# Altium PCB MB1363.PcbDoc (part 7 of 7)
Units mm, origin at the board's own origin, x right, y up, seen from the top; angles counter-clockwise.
Board outline 70 x 133.34 mm, 6 copper layers (Top Layer, Signal Layer 1, Signal Layer 2, Signal Layer 3, Signal Layer 4, Bottom Layer), stack 1.57 mm thick; 356 components, 294 nets, 1448 pads, 1107 vias.
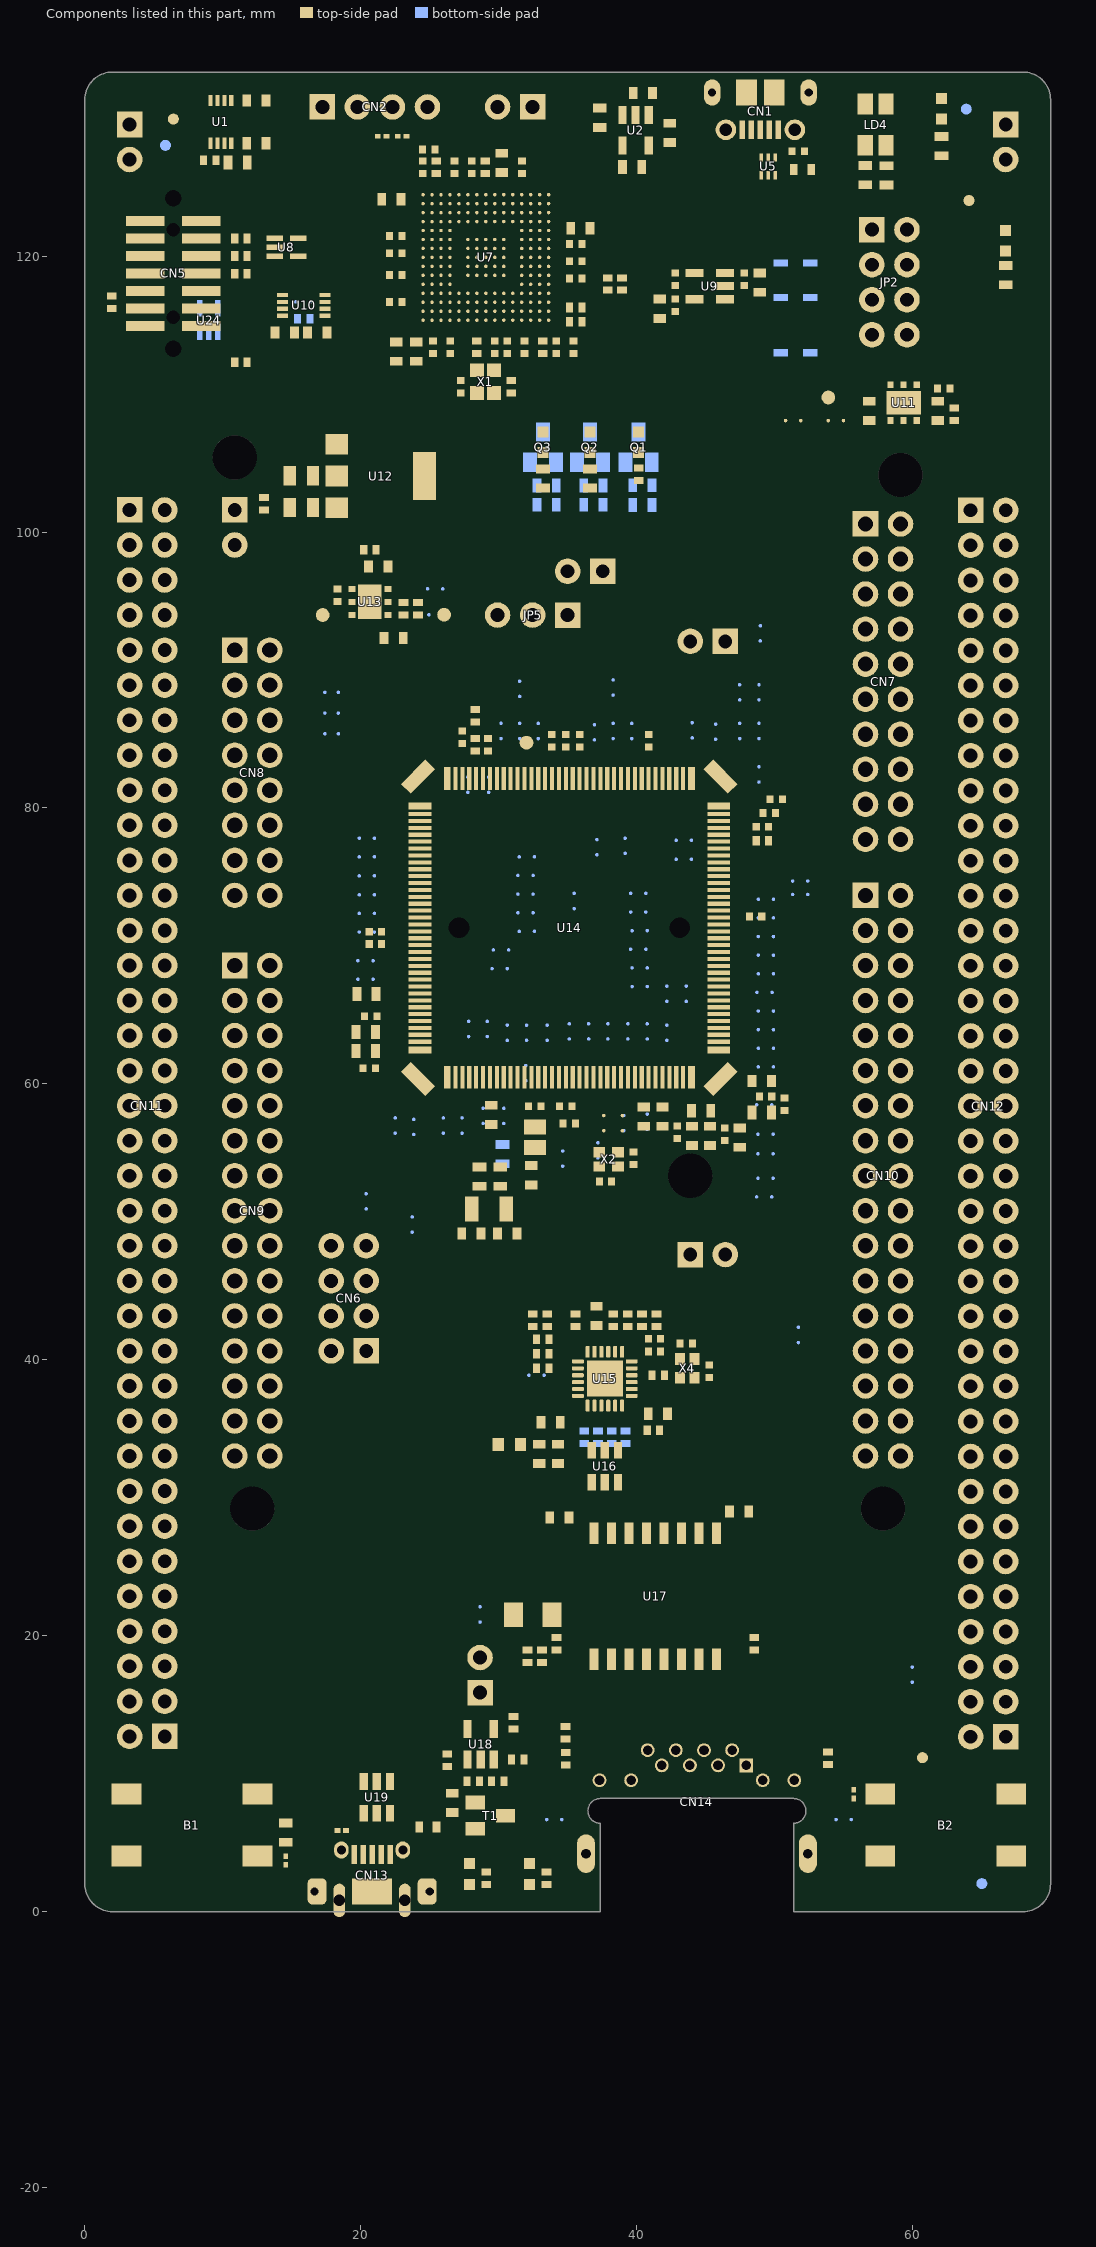
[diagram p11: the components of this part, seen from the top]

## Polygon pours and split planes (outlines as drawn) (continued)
GND on Top Layer "GND_L01_P090" (solid, remove dead copper, pour order 90): 1.577,133.34 0.116,131.879 0.116,107.629 20.166,107.629 20.666,108.129 25.866,108.129 26.4,107.595 26.4,100.163 25.991,99.754 16.291,99.754 15.416,100.629 13.866,100.629 13.866,107.629 0.116,107.629 0.116,1.629 1.616,0.129 35.366,0.129 35.366,12.379 28.991,12.379 28.616,12.004 28.616,8.979 27.016,7.379 26.266,7.379 25.366,6.479 25.366,4.379 23.866,2.879 21.866,2.879 21.366,3.379 21.366,5.379 25.116,9.129 25.116,14.629 25.366,14.879 35.866,14.879 35.866,8.379 53.366,8.379 53.369,0 68.237,0 69.866,1.629 69.866,106.879 60.116,106.879 59.616,107.379 59.616,108.629 59.866,108.879 63.116,108.879 63.116,111.879 62.616,112.379 59.016,112.379 58.15,113.245 58.15,124.05 58.979,124.879 63.616,124.879 64.366,124.129 64.366,119.379 64.866,118.879 67.396,118.879 67.396,118.849 67.866,118.379 67.866,107.629 67.616,107.379 67.616,107.129 69.866,107.129 69.866,131.879 68.405,133.34
5V on Signal Layer 2 "5V_L03_P060" (solid, remove dead copper, pour order 60): 58.575,113.8 59.496,112.879 62.391,112.879 63.616,114.104 63.616,124.429 61.641,126.404 50.866,126.404 48.191,123.729 41.841,123.729 36.066,117.954 26.266,117.954 23.766,120.454 4.541,120.454 1.091,117.004 1.091,113.079 1.691,112.479 3.941,112.479 5.466,114.004 38.241,114.004 44.791,120.554 57.771,120.554 58.63,119.695
5V_VIN on Signal Layer 2 "5V_VIN_L03_P034" (solid, remove dead copper, pour order 34): 19.366,104.779 20.316,105.729 20.316,107.504 20.666,107.854 25.641,107.854 26.016,107.479 26.016,100.629 25.666,100.279 20.491,100.279 20.291,100.479 20.291,102.429 19.591,103.129 19.366,103.354
VDD_MCU on Signal Layer 2 "VDD_MCU_L03_P088" (solid, remove dead copper, pour order 88): 18.166,87.354 17.916,87.104 17.916,86.479 18.266,86.129 24.191,86.129 27.941,82.379 41.591,82.379 42.166,82.954 42.166,85.304 41.641,85.829 31.891,85.829 30.366,87.354
5V on Signal Layer 2 "5V_L03_P062" (solid, remove dead copper, pour order 62): 15.866,14.304 13.316,11.754 1.441,11.754 1.091,11.404 1.091,9.979 1.716,9.354 14.791,9.354 17.816,12.379 27.091,12.379 27.366,12.654 27.366,14.079 27.141,14.304
VIN on Signal Layer 2 "VIN_L03_P082" (solid, remove dead copper, pour order 82): 12.441,104.079 12.016,104.079 11.191,103.254 11.191,101.679 12.566,100.304 19.716,100.304 19.991,100.579 19.991,102.279 19.366,102.904 18.196,104.074 17.341,104.074
GND on Signal Layer 2 "GND_L03_P092" (solid, remove dead copper, pour order 92): 2,133.34 1.986,133.354 1.55,133.354 -0.009,131.795 -0.009,117.504 0.166,117.329 0.916,117.329 4.391,120.804 23.941,120.804 26.391,118.354 35.841,118.354 41.566,124.079 48.041,124.079 50.816,126.854 62.041,126.854 64.016,124.879 64.016,114.004 62.841,112.829 62.841,112.079 69.816,112.079 69.816,132.004 68.491,133.329
GND on Signal Layer 2 "GND_L03_P094" (solid, remove dead copper, pour order 94): 0.091,113.329 0.391,113.329 1.491,112.229 4.166,112.229 5.641,113.704 38.666,113.704 45.116,120.154 57.671,120.154 58.225,119.6 58.225,113.675 59.346,112.554 62.566,112.554 62.841,112.829 69.592,112.829 69.866,112.555 69.866,81.879 43.116,81.879 42.366,82.629 42.366,83.559 42.366,85.429 41.766,86.029 31.966,86.029 26.366,91.629 26.366,107.654 25.716,108.304 20.491,108.304 19.891,107.704 19.891,105.829 18.466,104.404 11.741,104.404 10.716,103.379 10.716,100.529 10.566,100.379 0.341,100.379 0.091,100.629
GND on Signal Layer 2 "GND_L03_P096" (solid, remove dead copper, pour order 96): 26.666,100.854 25.916,100.104 12.241,100.104 10.4,101.945 10.4,103.669 8.751,103.669 7.491,104.929 0.216,104.929 0.116,104.829 0.116,11.404 0.253,11.266 0.579,11.266 1.316,12.004 13.166,12.004 15.691,14.529 27.316,14.529 27.616,14.229 27.616,12.179 69.916,12.179 69.941,12.204 69.941,81.577 69.59,81.929 43.066,81.929 42.366,82.629 41.741,82.004 27.741,82.004 23.891,85.854 18.141,85.854 17.616,86.379 17.616,87.204 18.091,87.679 30.287,87.679 30.301,87.693 26.666,91.329
GND on Signal Layer 2 "GND_L03_P098" (solid, remove dead copper, pour order 98): 0.566,10.029 1.616,8.979 15.041,8.979 18.116,12.054 27.141,12.054 27.666,12.579 34.091,12.579 34.416,12.904 34.416,13.054 35.291,13.929 69.891,13.929 69.941,13.879 69.941,1.204 68.816,0.079 1.216,0.079 0.216,1.079 0.216,10.004 0.191,10.029
GND on Signal Layer 1 "GND_L02_P020" (solid, remove dead copper, pour order 20): 35.266,9.866 36.068,10.668 52.748,10.668 53.666,9.75 53.666,8.429 53.491,8.254 53.491,0 69.037,0 69.416,0.379 70,0.963 70,132.345 69.005,133.34 68,133.34 -0.034,133.379 -0.034,0.929 0.895,0 35.266,0
GND on Signal Layer 4 "GND_L05_P050" (solid, remove dead copper, pour order 50): 35.369,10.569 36.425,11.625 52.4,11.625 53.425,10.6 53.364,10.263 53.501,10.126 53.5,10 53.525,9.975 53.541,9.975 53.541,0.054 53.591,0.079 68.541,0.079 69.866,1.404 69.866,131.829 68.466,133.229 1.791,133.254 1.516,133.254 0.041,131.779 0.041,1.629 1.591,0.079 35.369,0.079

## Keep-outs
Keep-Out Layer:
  lines w0.127: -0.004,1.999 ccw(c1.996,1.999) 1.996,-0.001

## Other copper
Top Layer:
  pour cut-out: 33.041,51.529 31.941,51.529 30.991,52.479 30.991,53.904 30.191,54.704 30.191,55.529 30.941,56.279 30.941,57.979 31.541,58.579 31.541,61.329 31.691,61.479 35.066,61.479 35.191,61.354 35.191,59.329 35.716,58.804 36.216,58.804 36.991,58.029 36.991,56.879 36.316,56.204 36.316,55.604 33.916,53.204 33.916,52.278 33.166,51.528
  pour cut-out: 24.316,126.629 23.271,126.629 21.721,125.079 21.721,122.206 21.536,122.021 21.536,113.804 22.001,113.339 26.226,113.339 26.891,114.004 26.891,115.779 27.446,116.334 28.79,116.334 29.716,115.408 29.716,113.904 30.416,113.204 35.791,113.204 36.291,113.704 36.291,121.204 36.116,121.379 31.791,121.379 31.791,122.379 32.49,123.078 32.49,126.627
  pour cut-out: 48.616,126.679 48.616,126.254 49.966,126.254 49.966,126.734 48.621,126.734 48.616,126.729
  pour cut-out: 35.366,17.35 53.366,17.35 53.366,-0.121 35.366,-0.121
  pour cut-out: 29.6,22.95 36.366,22.95 36.366,0 29.6,0
  text "1" at 67.218,104.184 h2 r90
Signal Layer 1:
  pour cut-out: 33.041,51.529 31.941,51.529 30.991,52.479 30.991,53.904 30.191,54.704 30.191,55.529 30.941,56.279 30.941,57.979 31.541,58.579 31.541,61.329 31.691,61.479 35.066,61.479 35.191,61.354 35.191,59.329 35.716,58.804 36.216,58.804 36.991,58.029 36.991,56.879 36.316,56.204 36.316,55.604 33.916,53.204 33.916,52.278 33.166,51.528
  pour cut-out: 35.366,17.35 53.366,17.35 53.366,-0.121 35.366,-0.121
  pour cut-out: 29.6,22.95 36.366,22.95 36.366,0 29.6,0
  text "2" at 67.218,105.434 h2 r90
Signal Layer 2:
  pour cut-out: 33.041,51.529 31.941,51.529 30.991,52.479 30.991,53.904 30.191,54.704 30.191,55.529 30.941,56.279 30.941,57.979 31.541,58.579 31.541,61.329 31.691,61.479 35.066,61.479 35.191,61.354 35.191,59.329 35.716,58.804 36.216,58.804 36.991,58.029 36.991,56.879 36.316,56.204 36.316,55.604 33.916,53.204 33.916,52.278 33.166,51.528
  pour cut-out: 35.366,17.35 53.366,17.35 53.366,-0.121 35.366,-0.121
  pour cut-out: 30.125,23.025 36.366,23.025 36.366,0 30.125,0
  text "3" at 67.218,106.934 h2 r90
Signal Layer 3:
  pour cut-out: 35.325,17.421 53.325,17.421 53.325,-0.05 35.325,-0.05
  text "4" at 67.218,109.184 h2 r90
Signal Layer 4:
  pour cut-out: 37.266,61.429 37.216,61.379 37.141,61.304 37.141,58.929 36.966,58.754 36.966,55.804 36.191,55.029 36.191,52.079 36.641,51.629 38.866,51.629 40.741,53.504 40.741,55.404 40.091,56.054 39.591,56.554 39.591,58.554 39.216,58.929 39.216,61.329 39.116,61.429
  pour cut-out: 30.741,61.429 30.666,61.354 30.666,58.729 30.391,58.454 30.391,57.929 30.066,57.604 29.066,57.604 28.841,57.379 28.841,56.604 27.666,55.429 27.666,52.729 26.866,51.929 26.866,48.504 27.541,47.829 30.966,47.829 31.791,48.654 31.791,51.154 30.841,52.104 30.841,54.204 30.641,54.404 30.291,54.404 30.216,54.479 30.216,55.554 31.016,56.354 31.016,58.129 31.591,58.704 31.591,61.354 31.516,61.429
  pour cut-out: 35.366,17.35 53.366,17.35 53.366,-0.121 35.366,-0.121
  pour cut-out: 32.3,8.2 36.366,8.2 36.366,0 32.3,0
  pour cut-out: 52.225,8.2 56.291,8.2 56.291,0 52.225,0
  text "5" at 67.218,110.684 h2 r90
Bottom Layer:
  pour cut-out: 32.541,19.7 35.475,19.7 35.475,0 32.541,0
  pour cut-out: 32.575,17.366 32.575,20.3 56.325,20.3 56.325,17.366
  pour cut-out: 56.459,0 53.525,0 53.525,20.225 56.459,20.225
  text "6" at 67.218,112.184 h2 r90
Multi-Layer:
  pour cut-out: 65.621,103.891 67.621,103.891 67.621,112.391 65.621,112.391
  pour cut-out: 36.441,28.325 36.441,17.359 46.266,17.359 46.266,28.325

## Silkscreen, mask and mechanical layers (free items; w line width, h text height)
Top Overlay:
  drawing of 1859 lines, arcs and shapes, not listed
  text "OVCR" at 60.186,132.098 h1.5
  text "COM" at 55.903,132.049 h1.5
  text "SWD" at 27.254,129.311 h1.5 r90
  text "STLK_RST" at 29.705,128.396 h0.91
  text "3V3" at 15.966,128.329 h1.5
  text "USB" at 45.027,127.236 h1.5
  text "STLK" at 15.394,127.064 h1.5
  text "GND" at 1.547,126.954 h1.5 r90
  text "GND" at 69.474,126.947 h1.5 r90
  text "PWR" at 44.861,126.086 h1.5
  text "ST-LINK V3" at 34.721,123.685 h1.5
  text "STLINK" at 50.42,121.407 h1.5
  text "VIN" at 52.85,118.795 h1.5
  text "5V" at 62.324,118.566 h1.5
  text "PWR" at 61.689,117.042 h1.5
  text "EXT" at 52.552,116.332 h1.5
  text "RX" at 0.706,114.299 h1.5
  text "TX" at 10.391,114.299 h1.5
  text "CHGR" at 51.18,113.769 h1.5
  text "MIPI10" at 4.326,111.224 h1.5
  text "3V3" at 52.749,110.764 h1.5
  text "5V_VIN" at 25.824,103.769 h1.5
  text "SCL" at 60.916,101.154 h1.2 r45
  text "User LEDs" at 34.039,101.13 h1.5
  text "D15" at 60.991,100.029 h1.2 r45
  text "VIN" at 17.315,99.842 h1.5
  text "3V3" at 36.435,98.66 h1.5
  text "SDA" at 60.916,98.379 h1.2 r45
  text "D14" at 60.991,97.229 h1.2 r45
  text "IDD" at 39.875,96.65 h1.5
  text "MCU_RST" at 7.776,96.466 h1.5
  text "+" at 62.291,95.379 h1.2 r45
  text "VREF" at 60.966,95.204 h1.2 r45
  text "I2S_A" at 54.017,94.409 h1.5 r90
  text "VDD" at 37.108,94.261 h1.5
  text "MCU" at 37.124,93.168 h1.5
  text "GND" at 60.891,92.779 h1.2 r45
  text "NC" at 7.741,92.154 h1.2 r315
  text "1V8" at 24.965,92.119 h1.5
  text "1V8" at 28.66,91.244 h1.5
  text "3V3" at 34.158,91.226 h1.5
  text "VDD" at 24.698,90.979 h1.5
  text "SCK" at 60.916,90.904 h1.2 r45
  text "VDD" at 28.393,90.104 h1.5
  text "VDD" at 33.891,90.086 h1.5
  text "D13" at 61.016,89.779 h1.2 r45
  text "IO" at 8.216,89.754 h1.2 r315
  text "RMII TXD1" at 41.862,89.533 h1.5
  text "REF" at 7.491,89.004 h1.2 r315
  text "MISO" at 60.966,88.079 h1.2 r45
  text "NRST" at 7.116,86.904 h1.2 r315
  text "D12" at 61.016,86.879 h1.2 r45
  text "I2S_B" at 54.719,85.921 h1.5 r90
  text "MOSI" at 60.991,85.329 h1.2 r45
  text "D11" at 60.966,84.079 h1.2 r45
  text "3V3" at 7.716,83.904 h1.2 r315
  text "SDMMC" at 16.676,82.753 h1.5 r90
  text "CS" at 60.891,82.629 h1.2 r45
  text "D10" at 60.966,81.479 h1.2 r45
  text "5V" at 7.841,81.354 h1.2 r315
  text "PWM" at 60.991,80.104 h1.2 r45
  text "GND" at 7.441,79.054 h1.2 r315
  text "D9" at 61.016,78.904 h1.2 r45
  text "SPI_B" at 54.151,78.837 h1.5 r90
  text "I/O" at 61.016,77.429 h1.2 r45
  text "GND" at 7.416,76.479 h1.2 r315
  text "D8" at 61.016,76.229 h1.2 r45
  text "IO" at 16.64,74.292 h1.5 r90
  text "I/O" at 61.041,74.204 h1.2 r45
  text "VIN" at 7.466,73.879 h1.2 r315
  text "AVDD" at 51.445,73.179 h1.5
  text "D7" at 61.041,72.954 h1.2 r45
  text "PWM" at 61.016,71.554 h1.2 r45
  text "AGND" at 51.342,70.602 h1.5
  text "D6" at 61.041,70.404 h1.2 r45
  text "A0" at 7.758,69.168 h1.2 r315
  text "PWM" at 61.041,69.029 h1.2 r45
  text "GND" at 52.309,68.223 h1.5
  text "D5" at 61.041,67.854 h1.2 r45
  text "A1" at 7.841,66.679 h1.2 r315
  text "I/O" at 61.016,66.429 h1.2 r45
  text "D4" at 61.041,65.204 h1.2 r45
  text "A2" at 7.866,64.129 h1.2 r315
  text "PWM" at 61.016,63.729 h1.2 r45
  text "D3" at 61.016,62.504 h1.2 r45
  text "A3" at 7.766,61.479 h1.2 r315
  text "USART" at 16.249,61.35 h1.5 r90
  text "I/O" at 61.016,61.129 h1.2 r45
  text "D2" at 61.041,59.954 h1.2 r45
  text "ADC_IN" at 54.018,59.134 h1.5 r90
  text "A4" at 7.816,59.004 h1.2 r315
  text "TX" at 60.992,58.483 h1.2 r45
  text "D1" at 60.991,57.254 h1.2 r45
  text "A5" at 7.766,56.429 h1.2 r315
  text "RX" at 61.016,55.729 h1.2 r45
  text "GND" at 14.885,55.395 h1.5
  text "D0" at 61.041,54.554 h1.2 r45
  text "COMP" at 8.392,50.222 h1.5 r90
  text "QSPI" at 53.866,49.124 h1.5 r90
  text "SAI_A" at 16.036,47.769 h1.5 r90
  text "PG" at 22.068,47.578 h1.5
  text "GND" at 24.847,47.553 h1.5
  text "VOUT" at 24.536,45.919 h1.5
  text "SW" at 21.903,45.271 h1.5
  text "RMII MDIO" at 42.543,45.101 h1.5
  text "I2C" at 8.534,44.676 h1.5 r90
  text "CORE" at 24.536,44.649 h1.5
  text "EN" at 21.996,42.744 h1.5
  text "VDD" at 24.872,42.73 h1.5
  text "TIMER" at 62.301,41.166 h1.5 r90
  text "GND" at 7.366,41.129 h1.2 r315
  text "V1" at 21.996,40.204 h1.5
  text "GND" at 52.309,40.207 h1.5
  text "3V3" at 25.093,40.186 h1.5
  text "SAI_B" at 16,37.601 h1.5 r90
  text "CAN" at 8.356,35.361 h1.5 r90
  text "TIMER" at 54.094,33.405 h1.5 r90
  text "IO" at 14.929,32.577 h1.5
  text "IO" at 8.202,32.51 h1.5
  text "USB PWR EN" at 28.325,20.05 h1.5 r90
  text "MB1363C" at 51.85,18.252 h2
  text "Nucleo" at 8.344,16.62 h3.3
  text "GND" at 64.243,10.076 h1.5
  text "GND" at 3.214,9.991 h1.5
  text "RESET" at 60.307,1.922 h1.5
  text "USER" at 6,1.9 h1.5
  text "User" at 13.205,1.729 h1.5
  text "USB" at 13.229,0.491 h1.5
  text "OVCR" at 26.258,0.329 h1.5
  text "VBUS" at 31.537,0.337 h1.5
Bottom Overlay:
  lines w0.12: 32.077,58.881 32.077,59.33
  lines w0.127: 30.875,16.45 30.875,25.45 55.875,25.45 55.875,16.45 30.875,16.45
  text "GND" at 68.326,127 h1.5 r270
  text "GND" at 0.741,126.829 h1.5 r270
  text "CN12" at 65.375,103.25 h1.5
  text "CN11" at 6.265,103.098 h1.5
  text "CN7" at 57.199,102.184 h1.5
  text "PC8" at 69.591,102.183 h1.2 r45
  text "PC11" at 9.533,101.167 h1.2
  text "PC10" at 1.766,100.979 h1.2 r315
  text "PC9" at 62.961,100.938 h1.2
  text "PC6" at 69.743,99.872 h1.2 r45
  text "PC12" at 1.791,98.579 h1.2 r315
  text "PD2" at 9.088,98.525 h1.2
  text "PB8" at 62.961,98.398 h1.2
  text "PC5" at 69.769,97.23 h1.2 r45
  text "3V3" at 1.866,96.504 h1.2 r315
  text "E5V" at 9.088,95.935 h1.2
  text "PB9" at 62.961,95.858 h1.2
  text "VDD" at 1.671,95.381 h1.2 r315
  text "U5V" at 69.667,94.563 h1.2 r45
  text "GND" at 9.088,93.445 h1.2
  text "BT0" at 1.595,93.318 h1.2 r315
  text "CN8" at 13.547,92.934 h1.5
  text "VREF+" at 62.69,92.664 h1.2 r315
  text "PD8" at 69.667,92.099 h1.2 r45
  text "NC" at 8.391,91.054 h1.2
  text "PF6" at 1.671,90.778 h1.2 r315
  text "GND" at 62.961,90.778 h1.2
  text "PA12" at 69.769,89.153 h1.2 r45
  text "+3V3" at 9.748,88.365 h1.2
  text "PA5" at 62.961,88.238 h1.2
  text "PF7" at 1.671,88.137 h1.2 r315
  text "PA11" at 69.489,86.41 h1.2 r45
  text "PA6" at 62.961,85.698 h1.2
  text "NRST" at 9.698,85.648 h1.2
  text "PA13" at 2.078,84.911 h1.2 r315
  text "PB12" at 69.591,83.895 h1.2 r45
  text "3V3" at 9.088,83.285 h1.2
  text "PA7" at 62.961,83.158 h1.2
  text "PA14" at 2.078,82.346 h1.2 r315
  text "PB11" at 69.642,81.38 h1.2 r45
  text "+5V" at 9.088,80.695 h1.2
  text "PB6" at 62.961,80.618 h1.2
  text "PA15" at 2.078,79.856 h1.2 r315
  text "GND" at 69.769,79.323 h1.2 r45
  text "GND" at 9.088,78.231 h1.2
  text "PC7" at 62.961,78.078 h1.2
  text "GND" at 1.671,78.053 h1.2 r315
  text "PB2" at 69.642,76.783 h1.2 r45
  text "GND" at 9.088,75.691 h1.2
  text "PA9" at 62.961,75.538 h1.2
  text "PB7" at 1.671,75.513 h1.2 r315
  text "CN10" at 59.578,75.041 h1.5
  text "PB1" at 69.489,74.065 h1.2 r45
  text "VIN" at 8.936,73.024 h1.2
  text "PA8" at 62.961,72.998 h1.2
  text "PC13" at 2.078,72.313 h1.2 r315
  text "PB15" at 69.591,71.373 h1.2 r45
  text "NC" at 8.466,70.704 h1.2
  text "PB10" at 62.961,70.458 h1.2
  text "CN9" at 13.647,69.951 h1.5
  text "PC14" at 2.078,69.696 h1.2 r315
  text "PB14" at 69.642,68.757 h1.2 r45
  text "PA0" at 9.088,68.096 h1.2
  text "PB4" at 62.961,67.918 h1.2
  text "PC15" at 1.9,67.36 h1.2 r315
  text "PB13" at 69.794,66.344 h1.2 r45
  text "PA1" at 8.783,65.505 h1.2
  text "PB5" at 62.961,65.378 h1.2
  text "OSCI" at 2.078,64.642 h1.2 r315
  text "AGND" at 69.86,64.007 h1.2 r45
  text "PA4" at 9.088,63.067 h1.2
  text "PB3" at 62.961,62.838 h1.2
  text "OSCO" at 2.078,62.102 h1.2 r315
  text "PC4" at 69.616,61.695 h1.2 r45
  text "PB0" at 9.088,60.425 h1.2
  text "PA10" at 62.961,60.298 h1.2
  text "VBAT" at 2.078,59.536 h1.2 r315
  text "NC" at 69.391,57.979 h1.2
  text "PC1" at 8.783,57.809 h1.2
  text "PA2" at 62.961,57.758 h1.2
  text "PC2" at 1.671,57.454 h1.2 r315
  text "NC" at 69.391,55.504 h1.2
  text "PC0" at 9.088,55.32 h1.2
  text "PA3" at 62.961,55.218 h1.2
  text "PC3" at 1.671,54.863 h1.2 r315
  text "PE8" at 69.616,53.847 h1.2 r45
  text "PD3" at 9.088,52.755 h1.2
  text "GND" at 62.961,52.678 h1.2
  text "PD4" at 1.595,52.628 h1.2 r315
  text "PF10" at 69.87,51.332 h1.2 r45
  text "NC" at 8.491,50.379 h1.2
  text "PD13" at 62.961,50.138 h1.2
  text "PD5" at 1.57,50.113 h1.2 r315
  text "PE7" at 69.667,48.716 h1.2 r45
  text "NC" at 8.516,47.904 h1.2
  text "PD6" at 1.57,47.598 h1.2 r315
  text "PD12" at 62.961,47.598 h1.2
  text "PD14" at 69.819,46.176 h1.2 r45
  text "PE2" at 9.088,45.16 h1.2
  text "PD7" at 1.519,45.135 h1.2 r315
  text "PD11" at 62.961,45.058 h1.2
  text "PD15" at 69.667,43.509 h1.2 r45
  text "PE4" at 9.088,42.747 h1.2
  text "PE3" at 1.544,42.544 h1.2 r315
  text "PE10" at 62.961,42.518 h1.2
  text "PF14" at 69.718,40.994 h1.2 r45
  text "GND" at 1.595,40.105 h1.2 r315
  text "PE12" at 62.961,39.978 h1.2
  text "PE5" at 9.088,39.928 h1.2
  text "PE9" at 69.667,38.556 h1.2 r45
  text "NC" at 1.966,37.729 h1.2
  text "NC" at 8.566,37.679 h1.2
  text "PE14" at 62.961,37.438 h1.2
  text "GND" at 69.667,36.041 h1.2 r45
  text "NC" at 2.016,35.179 h1.2
  text "PF8" at 9.088,35 h1.2
  text "PE15" at 62.961,34.898 h1.2
  text "PE11" at 69.794,33.578 h1.2 r45
  text "PF9" at 9.088,32.46 h1.2
  text "PD1" at 1.671,32.384 h1.2 r315
  text "PE13" at 62.961,32.358 h1.2
  text "NC" at 8.591,30.129 h1.2
  text "NC" at 62.941,30.054 h1.2
  text "NC" at 69.441,30.054 h1.2
  text "PD0" at 1.671,29.793 h1.2 r315
  text "PF15" at 69.819,28.32 h1.2 r45
  text "NC" at 1.916,27.554 h1.2
  text "GND" at 9.191,27.504 h1.2
  text "NC" at 62.991,27.479 h1.2
  text "PF11" at 69.642,25.704 h1.2 r45
  text "PE6" at 9.088,24.815 h1.2
  text "PG14" at 62.961,24.738 h1.2
  text "PE1" at 1.595,24.688 h1.2 r315
  text "PE0" at 69.667,23.468 h1.2 r45
  text "NC" at 8.566,22.454 h1.2
  text "GND" at 62.961,22.198 h1.2
  text "PG9" at 1.62,22.097 h1.2 r315
  text "PG8" at 69.616,20.827 h1.2 r45
  text "PG10" at 9.829,19.887 h1.2
  text "PD10" at 62.961,19.658 h1.2
  text "PG12" at 2.078,18.871 h1.2 r315
  text "PG7" at 62.925,17.475 h1.2
  text "NC" at 69.416,17.379 h1.2
  text "NC" at 2.016,17.354 h1.2
  text "PG13" at 9.829,17.322 h1.2
  text "PG6" at 69.743,15.975 h1.2 r45
  text "PG11" at 9.829,14.909 h1.2
  text "NC" at 62.841,14.754 h1.2
  text "PD9" at 1.671,14.477 h1.2 r315
  text "MB1363C" at 55.75,14.1 h2.5
  text "GND" at 67.075,10.1 h1.5
  text "GND" at 6.1,10 h1.5
Top Solder:
  region: 67.625,103.9 67.625,112.4 65.625,112.4 65.625,103.9
Bottom Solder:
  region: 67.625,103.9 67.625,112.4 65.625,112.4 65.625,103.9
M1-Board Shape:
  lines w0.1: 51.369,6.4 ccw(c51.369,6.4) 51.369,6.4 ; 51.369,6.4 ccw(c51.369,7.3) 52.269,7.3 ; 51.369,6.4 51.369,0 68,0 ; 52.269,7.3 ccw(c51.369,7.3) 51.369,8.2 37.369,8.2 ccw(c37.369,7.3) 36.469,7.3 ccw(c37.369,7.3) 37.369,6.4 37.369,0 2,0 cw(c2,2) 0,2 0,131.34 cw(c2,131.34) 2,133.34 68,133.34 cw(c68,131.34) 70,131.34 70,2 cw(c68,2) 68,0 ; 52.269,7.3 52.269,7.3 ; 68,0 68,0
Drill Drawing:
  drawing of 561 lines, arcs and shapes, not listed
  text "PCB SPECIFICATIONS :" at 2.036,176.169 h3
  text "PCB : TYPE 3" at 150.448,175.937 h3
  text "A.   MATERIAL :" at 2.036,172.169 h3
  text "FR-4" at 40.536,172.169 h3
  text "TG-170" at 57.036,172.169 h3
  text "X  TG-150" at 75.286,172.169 h3
  text "TG-140" at 91.286,172.169 h3
  text "ASPECT-RATIO, AXE Z :" at 150.448,170.437 h3
  text "B.   MATERIAL FAMILY :" at 2.036,169.169 h3
  text "N/A" at 40.536,169.169 h3
  text "C.   SOLDERMASK COLOR :" at 2.036,166.169 h3
  text "GREEN" at 40.536,166.169 h3
  text "X  WHITE" at 57.036,166.169 h3
  text "RED" at 75.286,166.169 h3
  text "BLACK" at 91.286,166.169 h3
  text "6:1 to 8:1 / LEVEL \"B\"" at 150.466,163.689 h3
  text "D.   SILKSCREEN COLOR :" at 2.036,163.169 h3
  text "WHITE" at 40.536,163.169 h3
  text "YELLOW" at 57.036,163.169 h3
  text "BLACK" at 75.286,163.169 h3
  text "X  Blue ink PANTONE 2955" at 91.286,163.169 h3
  text "E.   SURFACE FINISH :" at 2.036,160.169 h3
  text "X  ENIG" at 40.536,160.169 h3
  text "IMMERSION SILVER" at 57.036,160.169 h3
  text "IMMERSION TIN" at 91.286,160.169 h3
  text "MINIMUM PARAMETERS" at 150.493,158.088 h3
  text "HASL" at 40.536,157.169 h3
  text "HASL (PB-FREE)" at 57.036,157.169 h3
  text "GOLDEN FINGER" at 91.286,157.169 h3
  text "F.   IMPEDANCE CONTROL :" at 2.036,154.169 h3
  text "NO" at 40.536,154.169 h3
  text "X  YES  (SEE IMPEDANCE TABLE FOR DETAIL INFORMATION)" at 57.036,154.169 h3
  text "DEFAULT" at 150.493,152.588 h3
  text "G.   THROUGH VIA :" at 2.036,151.169 h3
  text "PLUG THE VIAS WHICH ARE COVERED WITH SOLDERMASK ONE OR TWO SIDE." at 40.536,151.169 h3
  text "PLUG MATERIAL :" at 40.536,148.169 h3
  text "X  SOLDERMASK" at 66.036,148.169 h3
  text "NON-CONDUCTIVE EPOXY." at 91.286,148.169 h3
  text "TRACKS : 0.120mm           / GAPS : 0.120mm" at 150.493,146.838 h3
  text "H.   STACK-UP :" at 2.036,145.169 h3
  text "SEE LAYER STACK-UP SEQUENCE FOR OVERALL THICKNESS." at 40.536,145.169 h3
  text "Layer" at 79.741,134.779 h2
  text "Name" at 88.115,134.779 h2
  text "Material" at 104.312,134.779 h2
  text "Thickness" at 118.866,134.779 h2
  text "Constant" at 130.821,134.779 h2
  text "Board Layer Stack" at 141.885,134.779 h2
  text "IMPEDANCE TABLE    RMII" at 163.739,134.594 h3
  text "1" at 79.741,130.779 h2
  text "Top Overlay" at 88.115,130.779 h2
  text "LAYER" at 167.989,129.594 h3
  text "TRACE" at 184.239,129.594 h3
  text "SPACING" at 194.739,129.594 h3
  text "IMPEDANCE" at 208.239,129.594 h3
  text "IMPEDANCE" at 225.239,129.594 h3
  text "TOL." at 243.989,129.594 h3
  text "(mm)" at 198.064,127.119 h2.5
  text "(mm)" at 186.239,127.069 h2.5
  text "(Single ended)" at 208.739,126.844 h2.5
  text "(Differential)" at 226.489,126.844 h2.5
  text "2" at 79.741,126.779 h2
  text "Top Solder" at 88.115,126.779 h2
  text "Solder Resist" at 104.312,126.779 h2
  text "0,015mm" at 118.866,126.779 h2
  text "3,5" at 130.821,126.779 h2
  text "+/- 15%" at 243.044,123.204 h3
  text "0.127" at 185.214,123.119 h3
  text "TOP/BOTTOM" at 164.219,123.079 h3
  text "n/a" at 197.239,123.094 h3
  text "50 ohm" at 211.594,123.029 h3
  text "n/a" at 231.144,122.979 h3
  text "3" at 79.741,122.779 h2
  text "Top Layer" at 88.115,122.779 h2
  text "Copper" at 104.312,122.779 h2
  text "0,042mm" at 118.866,122.779 h2
  text "+/- 15%" at 243.049,119.689 h3
  text "0.102" at 185.219,119.604 h3
  text "n/a" at 197.244,119.579 h3
  text "LAYER 3" at 166.164,119.544 h3
  text "50 ohm" at 211.599,119.514 h3
  text "n/a" at 231.149,119.464 h3
  text "4" at 79.741,118.779 h2
  text "Dielectric 1" at 88.115,118.779 h2
  text "FR-4" at 104.312,118.779 h2
  text "0,099mm" at 118.866,118.779 h2
  text "4,2" at 130.821,118.779 h2
  text "5" at 79.741,114.779 h2
  text "Signal Layer 1" at 88.115,114.779 h2
  text "Copper" at 104.312,114.779 h2
  text "0,035mm" at 118.866,114.779 h2
  text "IMPEDANCE TABLE    RD / RX / TD / TX" at 163.739,114.274 h3
  text "6" at 79.741,110.779 h2
  text "Dielectric 2" at 88.115,110.779 h2
  text "0,102mm" at 118.866,110.779 h2
  text "4,2" at 130.821,110.779 h2
  text "LAYER" at 167.989,109.655 h3
  text "TRACE" at 184.239,109.655 h3
  text "SPACING" at 194.739,109.655 h3
  text "IMPEDANCE" at 208.239,109.655 h3
  text "IMPEDANCE" at 225.239,109.655 h3
  text "TOL." at 243.989,109.655 h3
  text "(mm)" at 198.064,107.18 h2.5
  text "(mm)" at 186.239,107.13 h2.5
  text "(Single ended)" at 208.739,106.905 h2.5
  text "(Differential)" at 226.489,106.905 h2.5
  text "7" at 79.741,106.779 h2
  text "Signal Layer 2" at 88.115,106.779 h2
  text "Copper" at 104.312,106.779 h2
  text "0,035mm" at 118.866,106.779 h2
  text "+/- 15%" at 243.044,103.265 h3
  text "0.130" at 185.214,103.18 h3
  text "TOP/BOTTOM" at 164.219,103.14 h3
  text "0.251" at 197.239,103.155 h3
  text "n/a" at 211.594,103.09 h3
  text "100 ohm" at 227.68,103.041 h3
  text "8" at 79.741,102.779 h2
  text "Dielectric 3" at 88.115,102.779 h2
  text "0,946mm" at 118.866,102.779 h2
  text "4,2" at 130.821,102.779 h2
  text "+/- 15%" at 243.049,99.75 h3
  text "0.104" at 185.219,99.665 h3
  text "0.277" at 197.244,99.64 h3
  text "LAYER 3" at 166.164,99.605 h3
  text "100 ohm" at 227.68,99.612 h3
  text "n/a" at 211.599,99.575 h3
  text "9" at 79.741,98.779 h2
  text "Signal Layer 3" at 88.115,98.779 h2
  text "Copper" at 104.312,98.779 h2
  text "0,035mm" at 118.866,98.779 h2
  text "IMPEDANCE TABLE   USB FS, USB HS USER, USB HS STLINK" at 163.739,94.843 h3
  text "10" at 79.741,94.779 h2
  text "Dielectric 4" at 88.115,94.779 h2
  text "0,102mm" at 118.866,94.779 h2
  text "4,2" at 130.821,94.779 h2
  text "11" at 79.741,90.779 h2
  text "Signal Layer 4" at 88.115,90.779 h2
  text "Copper" at 104.312,90.779 h2
  text "0,035mm" at 118.866,90.779 h2
  text "LAYER" at 167.989,89.843 h3
  text "TRACE" at 184.239,89.843 h3
  text "SPACING" at 194.739,89.843 h3
  text "IMPEDANCE" at 208.239,89.843 h3
  text "IMPEDANCE" at 225.239,89.843 h3
  text "TOL." at 243.989,89.843 h3
  text "(mm)" at 198.064,87.368 h2.5
  text "(mm)" at 186.239,87.318 h2.5
  text "(Single ended)" at 208.739,87.093 h2.5
  text "(Differential)" at 226.489,87.093 h2.5
  text "12" at 79.741,86.779 h2
  text "Dielectric 5" at 88.115,86.779 h2
  text "0,099mm" at 118.866,86.779 h2
  text "4,2" at 130.821,86.779 h2
  text "+/- 15%" at 243.044,83.453 h3
  text "0.155" at 185.214,83.368 h3
  text "TOP/BOTTOM" at 164.219,83.328 h3
  text "0.226" at 197.239,83.343 h3
  text "n/a" at 211.594,83.278 h3
  text "90 ohm" at 227.68,83.102 h3
  text "13" at 79.741,82.779 h2
  text "Bottom Layer" at 88.115,82.779 h2
  text "Copper" at 104.312,82.779 h2
  text "0,042mm" at 118.866,82.779 h2
  text "+/- 15%" at 243.049,79.938 h3
  text "0.130" at 185.219,79.853 h3
  text "0.251" at 197.244,79.828 h3
  text "LAYER 3" at 166.164,79.793 h3
  text "90 ohm" at 227.68,79.8 h3
  text "n/a" at 211.599,79.763 h3
  text "14" at 79.741,78.779 h2
  text "Bottom Solder" at 88.115,78.779 h2
  text "Solder Resist" at 104.312,78.779 h2
  text "0,015mm" at 118.866,78.779 h2
  text "3,5" at 130.821,78.779 h2
  text "15" at 79.741,74.779 h2
  text "Bottom Overlay" at 88.115,74.779 h2
  text "Symbol" at 80.453,67.069 h2.4
  text "Count" at 89.856,67.069 h2.4
  text "Hole Size" at 100.478,67.069 h2.4
  text "Plated" at 119.727,67.069 h2.4
  text "Hole Type" at 127.983,67.069 h2.4
  text "Drill Layer Pair" at 139.996,67.069 h2.4
  text "Hole Length" at 162.752,67.069 h2.4
  text "Routed Path Length" at 181.03,67.069 h2.4
  text "1098" at 89.856,62.924 h2
  text "0,200mm (7,87mil)" at 100.478,62.924 h2
  text "PTH" at 119.727,62.924 h2
  text "Round" at 127.983,62.924 h2
  text "Top Layer - Bottom Layer" at 139.996,62.924 h2
  text "-" at 162.752,62.924 h2
  text "-" at 181.03,62.924 h2
  text "9" at 89.856,58.779 h2
  text "0,300mm (11,81mil)" at 100.478,58.779 h2
  text "PTH" at 119.727,58.779 h2
  text "Round" at 127.983,58.779 h2
  text "Top Layer - Bottom Layer" at 139.996,58.779 h2
  text "-" at 162.752,58.779 h2
  text "-" at 181.03,58.779 h2
  text "4" at 89.856,54.634 h2
  text "0,600mm (23,62mil)" at 100.478,54.634 h2
  text "PTH" at 119.727,54.634 h2
  text "Slot" at 127.983,54.634 h2
  text "Top Layer - Bottom Layer" at 139.996,54.634 h2
  text "1,300mm (51,18mil)" at 162.752,54.634 h2
  text "0,700mm (27,56mil)" at 181.03,54.634 h2
  text "2" at 89.856,50.488 h2
  text "0,650mm (25,59mil)" at 100.478,50.488 h2
  text "PTH" at 119.727,50.488 h2
  text "Slot" at 127.983,50.488 h2
  text "Top Layer - Bottom Layer" at 139.996,50.488 h2
  text "0,850mm (33,47mil)" at 162.752,50.488 h2
  text "0,200mm (7,88mil)" at 181.03,50.488 h2
  text "12" at 89.856,46.343 h2
  text "0,700mm (27,56mil)" at 100.478,46.343 h2
  text "PTH" at 119.727,46.343 h2
  text "Round" at 127.983,46.343 h2
  text "Top Layer - Bottom Layer" at 139.996,46.343 h2
  text "-" at 162.752,46.343 h2
  text "-" at 181.03,46.343 h2
  text "2" at 89.856,42.198 h2
  text "0,700mm (27,56mil)" at 100.478,42.198 h2
  text "PTH" at 119.727,42.198 h2
  text "Slot" at 127.983,42.198 h2
  text "Top Layer - Bottom Layer" at 139.996,42.198 h2
  text "2,200mm (86,61mil)" at 162.752,42.198 h2
  text "1,500mm (59,06mil)" at 181.03,42.198 h2
  text "2" at 89.856,38.052 h2
  text "0,850mm (33,47mil)" at 100.478,38.052 h2
  text "NPTH" at 119.727,38.052 h2
  text "Slot" at 127.983,38.052 h2
  text "Top Layer - Bottom Layer" at 139.996,38.052 h2
  text "2,425mm (95,47mil)" at 162.752,38.052 h2
  text "1,575mm (62,01mil)" at 181.03,38.052 h2
  text "2" at 89.856,33.907 h2
  text "0,900mm (35,43mil)" at 100.478,33.907 h2
  text "PTH" at 119.727,33.907 h2
  text "Round" at 127.983,33.907 h2
  text "Top Layer - Bottom Layer" at 139.996,33.907 h2
  text "-" at 162.752,33.907 h2
  text "-" at 181.03,33.907 h2
  text "2" at 89.856,29.762 h2
  text "0,970mm (38,19mil)" at 100.478,29.762 h2
  text "NPTH" at 119.727,29.762 h2
  text "Round" at 127.983,29.762 h2
  text "Top Layer - Bottom Layer" at 139.996,29.762 h2
  text "-" at 162.752,29.762 h2
  text "-" at 181.03,29.762 h2
  text "B" at 79.665,29.508 h1.84
  text "183" at 89.856,25.617 h2
  text "1,000mm (39,37mil)" at 100.478,25.617 h2
  text "PTH" at 119.727,25.617 h2
  text "Round" at 127.983,25.617 h2
  text "Top Layer - Bottom Layer" at 139.996,25.617 h2
  text "-" at 162.752,25.617 h2
  text "-" at 181.03,25.617 h2
  text "100" at 89.856,21.471 h2
  text "1,100mm (43,31mil)" at 100.478,21.471 h2
  text "PTH" at 119.727,21.471 h2
  text "Round" at 127.983,21.471 h2
  text "Top Layer - Bottom Layer" at 139.996,21.471 h2
  text "-" at 162.752,21.471 h2
  text "-" at 181.03,21.471 h2
  text "2" at 89.856,17.326 h2
  text "1,190mm (46,85mil)" at 100.478,17.326 h2
  text "NPTH" at 119.727,17.326 h2
  text "Round" at 127.983,17.326 h2
  text "Top Layer - Bottom Layer" at 139.996,17.326 h2
  text "-" at 162.752,17.326 h2
  text "-" at 181.03,17.326 h2
  text "C" at 79.665,17.072 h1.84
  text "2" at 89.856,13.181 h2
  text "1,500mm (59,06mil)" at 100.478,13.181 h2
  text "NPTH" at 119.727,13.181 h2
  text "Round" at 127.983,13.181 h2
  text "Top Layer - Bottom Layer" at 139.996,13.181 h2
  text "-" at 162.752,13.181 h2
  text "-" at 181.03,13.181 h2
  text "5" at 89.856,9.035 h2
  text "3,200mm (125,98mil)" at 100.478,9.035 h2
  text "NPTH" at 119.727,9.035 h2
  text "Round" at 127.983,9.035 h2
  text "Top Layer - Bottom Layer" at 139.996,9.035 h2
  text "-" at 162.752,9.035 h2
  text "-" at 181.03,9.035 h2
  text "1425 Total" at 89.856,4.89 h2
  text "Slot definitions :" at 80.453,1.988 h2
  text "Routed Path Length" at 94.094,1.988 h2
  text "= Calculated from tool start centre position to tool end centre position." at 110.99,1.988 h2
  text "Hole Length" at 94.094,0.33 h2
  text "= Routed Path Length + Tool Size = Slot length as defined in the PCB layout" at 104.718,0.33 h2

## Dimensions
10.866,105.4 to 59.126,104.13 on M4-Bottom Dimensions
43.886,53.33 to 59.126,104.13 on M4-Bottom Dimensions
3.246,126.99 to 3.246,12.69 on M4-Bottom Dimensions
10.866,33.01 to 3.246,12.69 on M4-Bottom Dimensions
3.246,12.69 to 2,-0.009 on M4-Bottom Dimensions
12.136,29.2 to 3.246,12.69 on M4-Bottom Dimensions
12.136,29.2 to 57.856,29.2 on M4-Bottom Dimensions
10.866,33.01 to 59.126,33.01 on M4-Bottom Dimensions
3.246,12.69 to 66.746,12.665 on M4-Bottom Dimensions
0,1.991 to 70,1.991 on M4-Bottom Dimensions
43.886,53.33 to 59.126,104.13 on M4-Bottom Dimensions
59.126,104.13 to 66.746,101.565 on M4-Bottom Dimensions
3.246,126.99 to 3.246,101.59 on M4-Bottom Dimensions
3.246,129.53 to 2,133.331 on M4-Bottom Dimensions
59.126,104.13 to 66.746,126.99 on M4-Bottom Dimensions
68,133.331 to 68,-0.009 on M4-Bottom Dimensions
10.866,105.4 to 3.246,101.59 on M4-Bottom Dimensions
10.866,105.409 to 3.246,101.599 on M3-Top Dimensions
68,133.34 to 68,0 on M3-Top Dimensions
59.126,104.139 to 66.746,126.999 on M3-Top Dimensions
3.246,129.539 to 2,133.34 on M3-Top Dimensions
3.246,126.999 to 3.246,101.599 on M3-Top Dimensions
59.126,104.139 to 66.746,101.574 on M3-Top Dimensions
43.886,53.339 to 59.126,104.139 on M3-Top Dimensions
0,2 to 70,2 on M3-Top Dimensions
5.786,12.699 to 64.206,12.674 on M3-Top Dimensions
10.866,33.019 to 59.126,33.019 on M3-Top Dimensions
12.136,29.209 to 57.856,29.209 on M3-Top Dimensions
12.136,29.209 to 5.786,12.699 on M3-Top Dimensions
5.786,12.699 to 2,0 on M3-Top Dimensions
10.866,33.019 to 5.786,12.699 on M3-Top Dimensions
3.246,126.999 to 5.786,12.699 on M3-Top Dimensions
43.886,53.339 to 59.126,104.139 on M3-Top Dimensions
10.866,105.409 to 59.126,104.139 on M3-Top Dimensions
0,131.34 to 70,131.34 on M2-Board Dimensions
2,0 to 2,133.34 on M2-Board Dimensions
